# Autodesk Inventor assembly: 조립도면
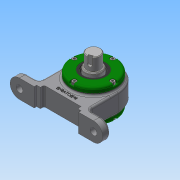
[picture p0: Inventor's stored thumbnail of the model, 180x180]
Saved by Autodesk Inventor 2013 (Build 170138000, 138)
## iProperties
Created: 2019-05
Part Number: 조립도면
Document SubType Name: Assembly
Designer: Administrator
Author: Administrator
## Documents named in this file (13)
- C:\Users\Administrator\Desktop\490504V1050\조립도면.iam
- C:\Users\Administrator\Desktop\490504V1050\본체.ipt
- C:\Users\Administrator\Desktop\490504V1050\490504V1050\개스킷.ipt
- C:\Users\Administrator\Desktop\490504V1050\490504V1050\그리스니플 M6.ipt
- 그리스니플  M6.ipt
- C:\Users\Administrator\Desktop\490504V1050\490504V1050\그리스니플개스킷.ipt
- C:\Users\Administrator\Desktop\490504V1050\490504V1050\베어링너트.ipt
- C:\Users\Administrator\Desktop\490504V1050\490504V1050\볼트 M4.ipt
- C:\Users\Administrator\Desktop\490504V1050\490504V1050\앵귤러 볼 베어링 7205.ipt
- C:\Users\Administrator\Desktop\490504V1050\490504V1050\오일 실 28 40 5 B.ipt
- C:\Users\Administrator\Desktop\490504V1050\490504V1050\축.ipt
- C:\Users\Administrator\Desktop\490504V1050\490504V1050\칼라.ipt
- C:\Users\Administrator\Desktop\490504V1050\490504V1050\커버.ipt
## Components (4 placed, 3 different names)
1. 개스킷:1
2. 그리스니플  M6:1 — 각도:2
3. 그리스니플개스킷:1
4. 개스킷:2
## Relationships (1: Angle 1)
- 각도:2 [Angle]: 그리스니플  M6:1
